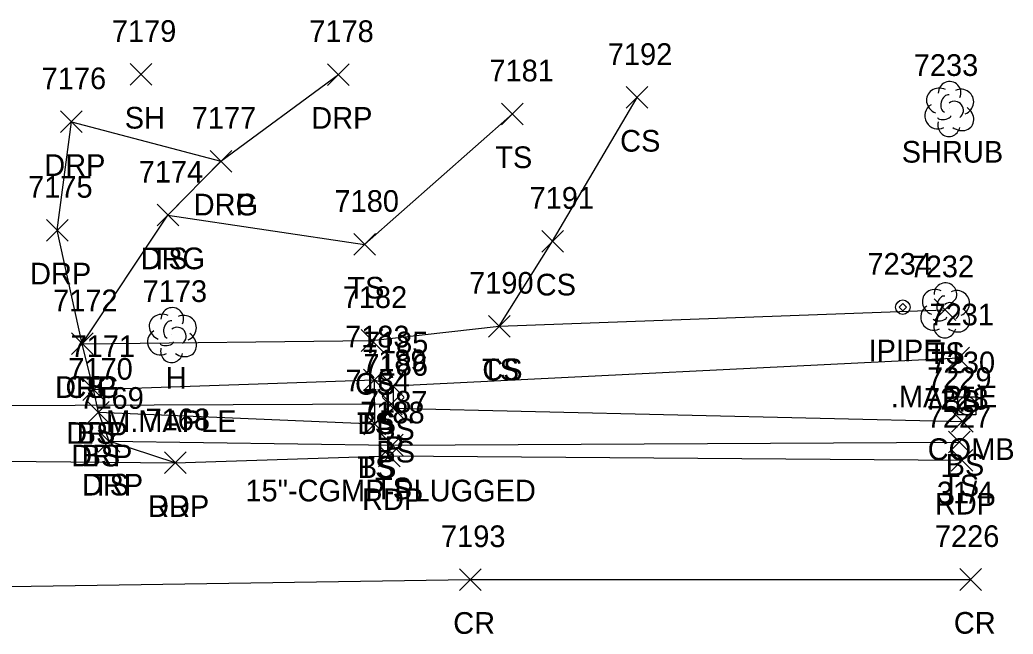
# Model space of a CAD drawing. Extents: x 1443912 to 1445411, y 621446 to 623693.
# Drawn here: x 1445317.3 to 1445409, y 622571 to 622627.6 of the extents above; entities that cross this region are included whole.
import ezdxf

# ---------------------------------------------------------------- set-up
doc = ezdxf.new("R2010")
doc.units = 0
for name, color, linetype in [('D_A', 7, 'Continuous'), ('D_C', 7, 'Continuous'), ('D_I', 7, 'Continuous'), ('D_TIC', 7, 'Continuous'), ('DCP', 7, 'Continuous'), ('L_A', 7, 'Continuous'), ('L_C', 7, 'Continuous'), ('L_I', 7, 'Continuous'), ('L_TIC', 7, 'Continuous'), ('LELB', 7, 'Continuous'), ('LSH', 7, 'Continuous'), ('LTD', 7, 'Continuous'), ('M_A', 7, 'Continuous'), ('M_I', 7, 'Continuous'), ('MPIP', 7, 'Continuous'), ('P_A', 7, 'Continuous'), ('P_I', 7, 'Continuous'), ('P_TIC', 7, 'Continuous'), ('PET', 7, 'Continuous'), ('PRC', 7, 'Continuous'), ('R_A', 7, 'Continuous'), ('R_I', 7, 'Continuous'), ('R_TIC', 7, 'Continuous'), ('RDG', 7, 'Continuous'), ('RDP', 7, 'Continuous'), ('U_A', 7, 'Continuous'), ('U_C', 7, 'Continuous'), ('U_I', 7, 'Continuous'), ('UP', 7, 'Continuous')]:
    doc.layers.add(name, color=color, linetype=linetype)

msp = doc.modelspace()

# ---------------------------------------------------------------- linework, layer by layer
at = {"layer": 'D_TIC'}
for points in [[(1445350.57, 622591.209), (1445352.57, 622593.209)], [(1445352.57, 622591.209), (1445350.57, 622593.209)]]:
    msp.add_lwpolyline(points, dxfattribs=at)
at = {"layer": 'DCP'}
msp.add_lwpolyline([(1445300.445, 622591.997), (1445351.57, 622592.209)], dxfattribs=at)
at = {"layer": 'L_TIC'}
for points in [[(1445327.469, 622621.604), (1445329.469, 622623.604)], [(1445329.469, 622621.604), (1445327.469, 622623.604)], [(1445373.238, 622619.476), (1445375.238, 622621.476)], [(1445375.238, 622619.476), (1445373.238, 622621.476)], [(1445361.743, 622617.959), (1445363.743, 622619.959)], [(1445363.743, 622617.959), (1445361.743, 622619.959)], [(1445329.94, 622608.628), (1445331.94, 622610.628)], [(1445331.94, 622608.628), (1445329.94, 622610.628)], [(1445348.098, 622605.923), (1445350.098, 622607.923)], [(1445350.098, 622605.923), (1445348.098, 622607.923)], [(1445365.449, 622606.208), (1445367.449, 622608.208)], [(1445367.449, 622606.208), (1445365.449, 622608.208)], [(1445401.657, 622599.888), (1445403.657, 622601.888)], [(1445403.657, 622599.888), (1445401.657, 622601.888)], [(1445360.519, 622598.374), (1445362.519, 622600.374)], [(1445362.519, 622598.374), (1445360.519, 622600.374)], [(1445360.519, 622598.374), (1445362.519, 622600.374)], [(1445362.519, 622598.374), (1445360.519, 622600.374)], [(1445322.044, 622596.756), (1445324.044, 622598.756)], [(1445324.044, 622596.756), (1445322.044, 622598.756)], [(1445348.768, 622597.053), (1445350.768, 622599.053)], [(1445350.768, 622597.053), (1445348.768, 622599.053)], [(1445402.927, 622595.447), (1445404.927, 622597.447)], [(1445404.927, 622595.447), (1445402.927, 622597.447)], [(1445348.987, 622593.415), (1445350.987, 622595.415)], [(1445350.987, 622593.415), (1445348.987, 622595.415)], [(1445348.987, 622593.415), (1445350.987, 622595.415)], [(1445350.987, 622593.415), (1445348.987, 622595.415)], [(1445323.079, 622592.52), (1445325.079, 622594.52)], [(1445325.079, 622592.52), (1445323.079, 622594.52)], [(1445350.722, 622592.864), (1445352.722, 622594.864)], [(1445352.722, 622592.864), (1445350.722, 622594.864)], [(1445350.722, 622592.864), (1445352.722, 622594.864)], [(1445352.722, 622592.864), (1445350.722, 622594.864)], [(1445323.529, 622590.436), (1445325.529, 622592.436)], [(1445325.529, 622590.436), (1445323.529, 622592.436)], [(1445350.743, 622590.798), (1445352.743, 622592.798)], [(1445352.743, 622590.798), (1445350.743, 622592.798)], [(1445350.743, 622590.798), (1445352.743, 622592.798)], [(1445352.743, 622590.798), (1445350.743, 622592.798)], [(1445349.022, 622589.364), (1445351.022, 622591.364)], [(1445351.022, 622589.364), (1445349.022, 622591.364)], [(1445349.022, 622589.364), (1445351.022, 622591.364)], [(1445351.022, 622589.364), (1445349.022, 622591.364)], [(1445403.278, 622589.585), (1445405.278, 622591.585)], [(1445405.278, 622589.585), (1445403.278, 622591.585)], [(1445324.518, 622587.751), (1445326.518, 622589.751)], [(1445326.518, 622587.751), (1445324.518, 622589.751)], [(1445402.99, 622587.679), (1445404.99, 622589.679)], [(1445404.99, 622587.679), (1445402.99, 622589.679)], [(1445350.641, 622587.403), (1445352.641, 622589.403)], [(1445352.641, 622587.403), (1445350.641, 622589.403)]]:
    msp.add_lwpolyline(points, dxfattribs=at)
at = {"layer": 'LELB'}
for points in [[(1445323.044, 622597.756), (1445349.768, 622598.053), (1445361.519, 622599.374), (1445366.449, 622607.208), (1445374.238, 622620.476)], [(1445330.94, 622609.628), (1445349.098, 622606.923), (1445362.743, 622618.959)], [(1445361.519, 622599.374), (1445402.657, 622600.888)], [(1445324.079, 622593.52), (1445349.987, 622594.415), (1445351.722, 622593.864), (1445403.927, 622596.447)], [(1445349.987, 622594.415), (1445350.022, 622590.364)], [(1445351.722, 622593.864), (1445351.743, 622591.798)], [(1445324.529, 622591.436), (1445350.022, 622590.364), (1445351.743, 622591.798), (1445404.278, 622590.585)], [(1445325.518, 622588.751), (1445351.641, 622588.403), (1445403.99, 622588.679)]]:
    msp.add_lwpolyline(points, dxfattribs=at)
at = {"layer": 'LSH'}
msp.add_line((1445403.041, 622619.462), (1445403.041, 622619.462), dxfattribs=at)
msp.add_line((1445403.041, 622619.462), (1445403.041, 622619.462), dxfattribs=at)
msp.add_arc((1445403.088, 622620.896), 1.047, 335.52715, 180.95627, dxfattribs=at)
for centre, major_axis, ratio, start_param, end_param in [((1445402.249, 622620.129), (1.21, -0.512), 0.895232, 1.570796, 4.712389), ((1445402.832, 622619.92), (-0.208, -0.792), 0.645439, 3.141593, 6.283185), ((1445404.082, 622620.046), (-1.141, -0.483), 0.949671, 1.570796, 4.712389), ((1445401.958, 622618.754), (0.584, -1.042), 0.959034, 3.141593, 6.283185), ((1445403.541, 622619.296), (-0.5, 0.667), 0.989748, 3.141593, 6.283185), ((1445404.041, 622618.629), (-1.09, 0.792), 0.841452, 1.570796, 4.712389), ((1445403.041, 622617.962), (0.265, 1.061), 0.942809, 1.570796, 4.712389), ((1445402.583, 622618.712), (-0.625, -0.083), 0.423636, 0, 3.141593)]:
    msp.add_ellipse(centre, major_axis=major_axis, ratio=ratio, start_param=start_param, end_param=end_param, dxfattribs=at)
at = {"layer": 'LTD'}
for p, q in [((1445402.657, 622600.888), (1445402.657, 622600.888)), ((1445402.657, 622600.888), (1445402.657, 622600.888)), ((1445331.301, 622598.604), (1445331.301, 622598.604)), ((1445331.301, 622598.604), (1445331.301, 622598.604))]:
    msp.add_line(p, q, dxfattribs=at)
for centre in [(1445402.704, 622602.322), (1445331.348, 622600.038)]:
    msp.add_arc(centre, 1.047, 335.52715, 180.95627, dxfattribs=at)
for centre, major_axis, ratio, start_param, end_param in [((1445401.866, 622601.554), (1.21, -0.512), 0.895232, 1.570796, 4.712389), ((1445403.699, 622601.471), (-1.141, -0.483), 0.949671, 1.570796, 4.712389), ((1445402.449, 622601.346), (-0.208, -0.792), 0.645439, 3.141593, 6.283185), ((1445403.158, 622600.721), (-0.5, 0.667), 0.989748, 3.141593, 6.283185), ((1445330.509, 622599.271), (1.21, -0.512), 0.895232, 1.570796, 4.712389), ((1445332.342, 622599.188), (-1.141, -0.483), 0.949671, 1.570796, 4.712389), ((1445401.574, 622600.179), (0.584, -1.042), 0.959034, 3.141593, 6.283185), ((1445403.658, 622600.054), (-1.09, 0.792), 0.841452, 1.570796, 4.712389), ((1445331.092, 622599.063), (-0.208, -0.792), 0.645439, 3.141593, 6.283185), ((1445402.658, 622599.388), (0.265, 1.061), 0.942809, 1.570796, 4.712389), ((1445402.199, 622600.138), (-0.625, -0.083), 0.423636, 0, 3.141593), ((1445330.218, 622597.896), (0.584, -1.042), 0.959034, 3.141593, 6.283185), ((1445331.801, 622598.438), (-0.5, 0.667), 0.989748, 3.141593, 6.283185), ((1445332.301, 622597.771), (-1.09, 0.792), 0.841452, 1.570796, 4.712389), ((1445330.843, 622597.854), (-0.625, -0.083), 0.423636, 0, 3.141593), ((1445331.301, 622597.104), (0.265, 1.061), 0.942809, 1.570796, 4.712389)]:
    msp.add_ellipse(centre, major_axis=major_axis, ratio=ratio, start_param=start_param, end_param=end_param, dxfattribs=at)
at = {"layer": 'MPIP'}
msp.add_lwpolyline([(1445399.102, 622601.128), (1445398.769, 622601.462), (1445398.435, 622601.128), (1445398.769, 622600.795)], close=True, dxfattribs=at)
msp.add_circle((1445398.769, 622601.128), 0.667, dxfattribs=at)
at = {"layer": 'P_TIC'}
for points in [[(1445330.619, 622585.772), (1445332.619, 622587.772)], [(1445332.619, 622585.772), (1445330.619, 622587.772)], [(1445350.379, 622586.403), (1445352.379, 622588.403)], [(1445352.379, 622586.403), (1445350.379, 622588.403)], [(1445403.24, 622585.997), (1445405.24, 622587.997)], [(1445405.24, 622585.997), (1445403.24, 622587.997)], [(1445357.841, 622574.991), (1445359.841, 622576.991)], [(1445359.841, 622574.991), (1445357.841, 622576.991)], [(1445404.048, 622575.003), (1445406.048, 622577.003)], [(1445406.048, 622575.003), (1445404.048, 622577.003)]]:
    msp.add_lwpolyline(points, dxfattribs=at)
at = {"layer": 'PET'}
msp.add_lwpolyline([(1444828.325, 622597.96), (1444848.504, 622596.752), (1444898.46, 622594.677), (1444911.129, 622594.321), (1444955.703, 622592.454), (1444994.25, 622591.157), (1445024.916, 622590.298), (1445058.354, 622589.126), (1445106.387, 622588.611), (1445145.413, 622587.835), (1445199.354, 622587.761), (1445245.806, 622587.569), (1445289.735, 622586.867), (1445302.68, 622587.056), (1445331.619, 622586.772), (1445351.379, 622587.403), (1445404.24, 622586.997)], dxfattribs=at)
at = {"layer": 'PRC'}
msp.add_lwpolyline([(1444773.111, 622588.757), (1444790.079, 622588.196), (1444813.693, 622587.068), (1444848.471, 622586.579), (1444897.837, 622583.54), (1444932.228, 622582.395), (1444986.667, 622580.693), (1445025.716, 622579.484), (1445065.673, 622578.343), (1445106.555, 622577.89), (1445145.901, 622577.113), (1445204.597, 622577.216), (1445219.997, 622576.877), (1445261.162, 622576.439), (1445312.233, 622575.287), (1445358.841, 622575.991), (1445405.048, 622576.003)], dxfattribs=at)
at = {"layer": 'R_TIC'}
for points in [[(1445345.685, 622621.588), (1445347.685, 622623.588)], [(1445347.685, 622621.588), (1445345.685, 622623.588)], [(1445321.04, 622617.236), (1445323.04, 622619.236)], [(1445323.04, 622617.236), (1445321.04, 622619.236)], [(1445334.837, 622613.592), (1445336.837, 622615.592)], [(1445336.837, 622613.592), (1445334.837, 622615.592)], [(1445334.837, 622613.592), (1445336.837, 622615.592)], [(1445336.837, 622613.592), (1445334.837, 622615.592)], [(1445329.94, 622608.628), (1445331.94, 622610.628)], [(1445331.94, 622608.628), (1445329.94, 622610.628)], [(1445319.733, 622607.225), (1445321.733, 622609.225)], [(1445321.733, 622607.225), (1445319.733, 622609.225)], [(1445322.044, 622596.756), (1445324.044, 622598.756)], [(1445324.044, 622596.756), (1445322.044, 622598.756)], [(1445322.044, 622596.756), (1445324.044, 622598.756)], [(1445324.044, 622596.756), (1445322.044, 622598.756)], [(1445323.079, 622592.52), (1445325.079, 622594.52)], [(1445325.079, 622592.52), (1445323.079, 622594.52)], [(1445323.529, 622590.436), (1445325.529, 622592.436)], [(1445325.529, 622590.436), (1445323.529, 622592.436)], [(1445324.518, 622587.751), (1445326.518, 622589.751)], [(1445326.518, 622587.751), (1445324.518, 622589.751)], [(1445330.619, 622585.772), (1445332.619, 622587.772)], [(1445332.619, 622585.772), (1445330.619, 622587.772)]]:
    msp.add_lwpolyline(points, dxfattribs=at)
at = {"layer": 'RDG'}
msp.add_lwpolyline([(1445323.044, 622597.756), (1445330.94, 622609.628), (1445335.837, 622614.592)], dxfattribs=at)
at = {"layer": 'RDP'}
msp.add_lwpolyline([(1445331.619, 622586.772), (1445325.518, 622588.751), (1445324.529, 622591.436), (1445324.079, 622593.52), (1445323.044, 622597.756), (1445320.733, 622608.225), (1445322.04, 622618.236), (1445335.837, 622614.592), (1445346.685, 622622.588)], dxfattribs=at)
at = {"layer": 'UP'}
for p, q in [((1445404.935, 622593.695), (1445404.685, 622592.862)), ((1445403.851, 622591.195), (1445403.851, 622592.862)), ((1445403.851, 622592.862), (1445405.518, 622592.862)), ((1445405.518, 622592.862), (1445405.518, 622591.195)), ((1445404.685, 622592.028), (1445404.685, 622592.028)), ((1445405.518, 622591.195), (1445403.851, 622591.195)), ((1445404.435, 622590.362), (1445404.685, 622591.195))]:
    msp.add_line(p, q, dxfattribs=at)
msp.add_circle((1445404.685, 622592.028), 0.833, dxfattribs=at)

# ---------------------------------------------------------------- texts
at = {"layer": 'D_A'}
msp.add_text('P', height=2, dxfattribs=at).set_placement((1445350.948, 622587.209))
at = {"layer": 'D_C'}
msp.add_text('15"-CGMP-PLUGGED', height=2, dxfattribs=at).set_placement((1445338.098, 622583.209))
at = {"layer": 'D_I'}
msp.add_text('7189', height=2, dxfattribs=at).set_placement((1445348.87, 622595.209))
at = {"layer": 'L_A'}
for s, p in [('SH', (1445326.957, 622617.604)), ('CS', (1445372.679, 622615.476)), ('SHRUB', (1445398.671, 622614.462)), ('TS', (1445361.152, 622613.959)), ('TS', (1445329.349, 622604.628)), ('CS', (1445364.89, 622602.208)), ('TS', (1445347.507, 622601.923)), ('TS', (1445401.067, 622595.888)), ('H', (1445402.091, 622595.888)), ('TS', (1445359.929, 622594.374)), ('CS', (1445359.96, 622594.374)), ('H', (1445330.734, 622593.604)), ('CS', (1445348.209, 622593.053)), ('CS', (1445321.485, 622592.756)), ('BS', (1445402.368, 622591.447)), ('TS', (1445348.396, 622589.415)), ('BS', (1445348.428, 622589.415)), ('BS', (1445322.52, 622588.52)), ('BS', (1445350.163, 622588.864)), ('BS', (1445350.163, 622588.864)), ('BS', (1445350.184, 622586.798)), ('BS', (1445350.184, 622586.798)), ('BS', (1445322.97, 622586.436)), ('TS', (1445348.432, 622585.364)), ('BS', (1445348.463, 622585.364)), ('BS', (1445402.719, 622585.585)), ('TS', (1445323.927, 622583.751)), ('TS', (1445350.051, 622583.403)), ('TS', (1445402.4, 622583.679))]:
    msp.add_text(s, height=2, dxfattribs=at).set_placement(p)
at = {"layer": 'L_C'}
for s, p in [('.MAPLE', (1445397.665, 622591.888)), ('M.MAPLE', (1445325.238, 622589.604))]:
    msp.add_text(s, height=2, dxfattribs=at).set_placement(p)
at = {"layer": 'L_I'}
for s, p in [('7179', (1445325.768, 622625.604)), ('7192', (1445371.545, 622623.476)), ('7233', (1445399.781, 622622.462)), ('7181', (1445360.617, 622621.959)), ('7174', (1445328.247, 622612.628)), ('7180', (1445346.318, 622609.923)), ('7191', (1445364.323, 622610.208)), ('7232', (1445399.398, 622603.888)), ('7232', (1445399.398, 622603.888)), ('7190', (1445358.74, 622602.374)), ('7190', (1445358.74, 622602.374)), ('7173', (1445328.608, 622601.604)), ('7172', (1445320.351, 622600.756)), ('7182', (1445347.075, 622601.053)), ('7231', (1445401.235, 622599.447)), ('7183', (1445347.294, 622597.415)), ('7183', (1445347.294, 622597.415)), ('7185', (1445349.029, 622596.864)), ('7185', (1445349.029, 622596.864)), ('7171', (1445321.954, 622596.52)), ('7186', (1445348.995, 622594.798)), ('7186', (1445348.995, 622594.798)), ('7170', (1445321.75, 622594.436)), ('7184', (1445347.329, 622593.364)), ('7184', (1445347.329, 622593.364)), ('7229', (1445401.011, 622593.585)), ('7169', (1445322.77, 622591.751)), ('7187', (1445348.948, 622591.403)), ('7228', (1445400.73, 622591.679))]:
    msp.add_text(s, height=2, dxfattribs=at).set_placement(p)
at = {"layer": 'M_A'}
msp.add_text('IPIPE', height=2, dxfattribs=at).set_placement((1445395.604, 622596.128))
at = {"layer": 'M_I'}
msp.add_text('7234', height=2, dxfattribs=at).set_placement((1445395.509, 622604.128))
at = {"layer": 'P_A'}
for s, p in [('RDP', (1445348.867, 622582.403)), ('RDP', (1445401.728, 622581.997)), ('RDP', (1445329.107, 622581.772)), ('CR', (1445357.274, 622570.991)), ('CR', (1445403.481, 622571.003))]:
    msp.add_text(s, height=2, dxfattribs=at).set_placement(p)
at = {"layer": 'P_I'}
for s, p in [('7188', (1445348.686, 622590.403)), ('7168', (1445328.879, 622589.772)), ('7227', (1445400.98, 622589.997)), ('7193', (1445356.148, 622578.991)), ('7226', (1445401.733, 622579.003))]:
    msp.add_text(s, height=2, dxfattribs=at).set_placement(p)
at = {"layer": 'R_A'}
for s, p in [('DRP', (1445344.173, 622617.588)), ('DRP', (1445319.528, 622613.236)), ('DRG', (1445333.325, 622609.592)), ('DRP', (1445333.325, 622609.592)), ('DRG', (1445328.428, 622604.628)), ('DRP', (1445318.221, 622603.225)), ('DRG', (1445320.532, 622592.756)), ('DRP', (1445320.532, 622592.756)), ('DRP', (1445321.568, 622588.52)), ('DRP', (1445322.018, 622586.436)), ('DRP', (1445323.006, 622583.751)), ('DRP', (1445329.107, 622581.772))]:
    msp.add_text(s, height=2, dxfattribs=at).set_placement(p)
at = {"layer": 'R_I'}
for s, p in [('7178', (1445343.992, 622625.588)), ('7176', (1445319.292, 622621.236)), ('7177', (1445333.144, 622617.592)), ('7177', (1445333.144, 622617.592)), ('7174', (1445328.247, 622612.628)), ('7175', (1445318.04, 622611.225)), ('7172', (1445320.351, 622600.756)), ('7172', (1445320.351, 622600.756)), ('7171', (1445321.954, 622596.52)), ('7170', (1445321.75, 622594.436)), ('7169', (1445322.77, 622591.751)), ('7168', (1445328.879, 622589.772))]:
    msp.add_text(s, height=2, dxfattribs=at).set_placement(p)
at = {"layer": 'U_A'}
msp.add_text('COMB', height=2, dxfattribs=at).set_placement((1445401.07, 622587.028))
at = {"layer": 'U_C'}
msp.add_text('31/4', height=2, dxfattribs=at).set_placement((1445401.913, 622583.028))
at = {"layer": 'U_I'}
msp.add_text('7230', height=2, dxfattribs=at).set_placement((1445401.338, 622595.028))

doc.saveas('drawing.dxf')
